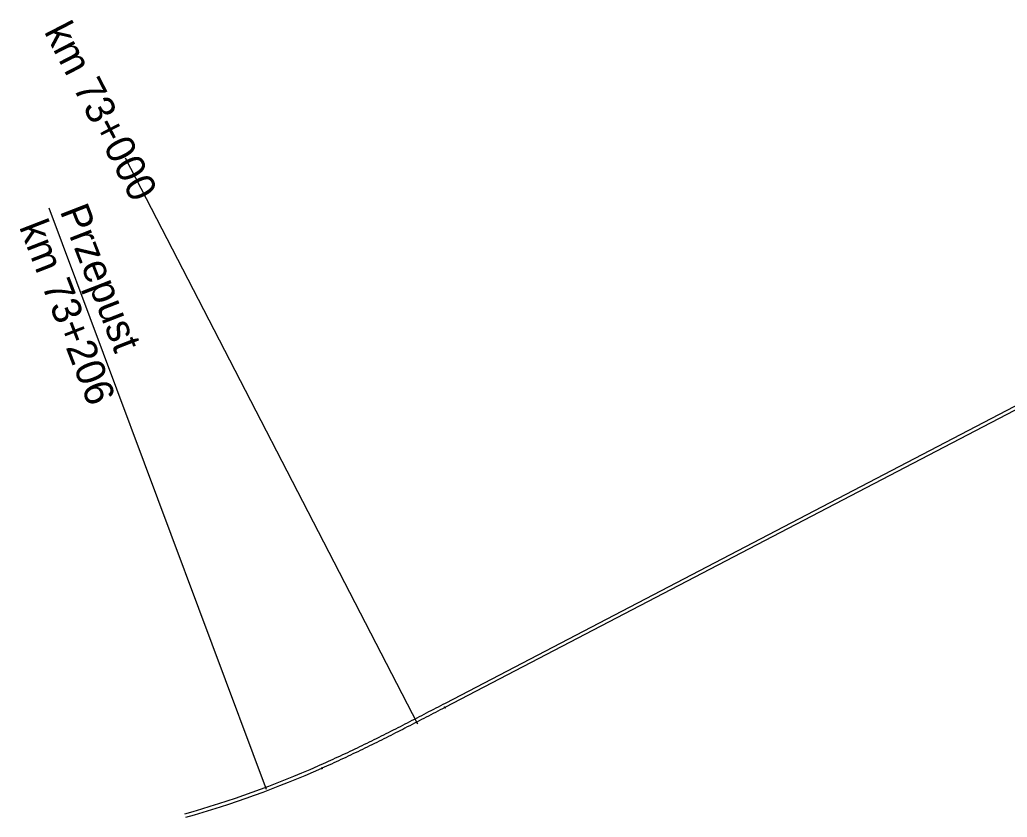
# Model space of a CAD drawing. Extents: x 6540591 to 6566579, y 5525343 to 5532423.
# Drawn here: x 6546011 to 6547196, y 5525886 to 5526843 of the extents above; entities that cross this region are included whole.
import ezdxf

# ---------------------------------------------------------------- set-up
doc = ezdxf.new("R2010")
doc.units = 0
for name, color, linetype in [('IR_ps_geometria', 7, 'Continuous'), ('TOR_PS_OPIS_T-hektometry projektowane', 7, 'Continuous'), ('TOR_PS_OPIS_T-opisy dodatkowe', 7, 'Continuous'), ('TOR_PS_T-tory projektowane', 7, 'Continuous')]:
    doc.layers.add(name, color=color, linetype=linetype)

msp = doc.modelspace()

# ---------------------------------------------------------------- linework, layer by layer
at = {"layer": 'IR_ps_geometria'}
for points in [[(6546521.1, 5526017.4), (6546521.2, 5526017.2), (6546521.3, 5526017.2), (6546521.3, 5526017.2), (6546521.3, 5526017.2), (6546521.4, 5526017.2), (6546521.4, 5526017.2), (6546521.4, 5526017.2), (6546521.4, 5526017.2), (6546521.5, 5526017.2), (6546521.5, 5526017.2), (6546521.5, 5526017.1), (6546521.5, 5526017.1), (6546521.6, 5526017.1), (6546521.6, 5526017), (6546521.6, 5526017), (6546521.6, 5526017), (6546521.6, 5526016.9), (6546521.6, 5526016.9), (6546521.6, 5526016.9), (6546521.6, 5526016.9), (6546521.6, 5526016.8), (6546521.5, 5526016.8), (6546521.5, 5526016.8), (6546521.5, 5526016.8), (6546521.5, 5526016.7), (6546521.4, 5526016.7), (6546521.4, 5526016.7), (6546521.4, 5526016.7), (6546521.3, 5526016.7), (6546521.3, 5526016.7), (6546521.3, 5526016.7), (6546521.2, 5526016.7), (6546521.2, 5526016.7), (6546521.2, 5526016.8), (6546521.2, 5526016.8), (6546521.1, 5526016.8), (6546521.1, 5526016.8), (6546521.1, 5526016.9), (6546521.1, 5526016.9), (6546521.1, 5526016.9), (6546521.1, 5526017), (6546521.1, 5526017), (6546521.1, 5526017), (6546521.1, 5526017.1), (6546521.1, 5526017.1), (6546521.1, 5526017.1), (6546521.2, 5526017.1), (6546521.2, 5526017.2), (6546521.2, 5526017.2), (6546521, 5526017.6), (6546521, 5526017.6), (6546520.9, 5526017.6), (6546520.9, 5526017.6), (6546520.9, 5526017.6), (6546520.8, 5526017.6), (6546520.8, 5526017.6), (6546520.8, 5526017.6), (6546520.7, 5526017.6), (6546520.7, 5526017.7), (6546520.7, 5526017.7), (6546520.7, 5526017.7), (6546520.7, 5526017.7), (6546520.6, 5526017.8), (6546520.6, 5526017.8), (6546520.6, 5526017.8), (6546520.6, 5526017.9), (6546520.6, 5526017.9), (6546520.6, 5526017.9), (6546520.7, 5526018), (6546520.7, 5526018), (6546520.7, 5526018), (6546520.7, 5526018), (6546520.7, 5526018.1), (6546520.8, 5526018.1), (6546520.8, 5526018.1), (6546520.8, 5526018.1), (6546520.9, 5526018.1), (6546520.9, 5526018.1), (6546520.9, 5526018.1), (6546521, 5526018.1), (6546521, 5526018.1), (6546521, 5526018.1), (6546521, 5526018), (6546521.1, 5526018), (6546521.1, 5526018), (6546521.1, 5526018), (6546521.1, 5526017.9), (6546521.1, 5526017.9), (6546521.1, 5526017.9), (6546521.1, 5526017.8), (6546521.1, 5526017.8), (6546521.1, 5526017.8), (6546521.1, 5526017.7), (6546521.1, 5526017.7), (6546521.1, 5526017.7), (6546521, 5526017.7), (6546521, 5526017.6), (6546521, 5526017.6)], [(6546521.1, 5526017.4), (6546521.2, 5526017.2), (6546521.3, 5526017.2), (6546521.3, 5526017.2), (6546521.3, 5526017.2), (6546521.4, 5526017.2), (6546521.4, 5526017.2), (6546521.4, 5526017.2), (6546521.4, 5526017.2), (6546521.5, 5526017.2), (6546521.5, 5526017.2), (6546521.5, 5526017.1), (6546521.5, 5526017.1), (6546521.6, 5526017.1), (6546521.6, 5526017), (6546521.6, 5526017), (6546521.6, 5526017), (6546521.6, 5526016.9), (6546521.6, 5526016.9), (6546521.6, 5526016.9), (6546521.6, 5526016.9), (6546521.6, 5526016.8), (6546521.5, 5526016.8), (6546521.5, 5526016.8), (6546521.5, 5526016.8), (6546521.5, 5526016.7), (6546521.4, 5526016.7), (6546521.4, 5526016.7), (6546521.4, 5526016.7), (6546521.3, 5526016.7), (6546521.3, 5526016.7), (6546521.3, 5526016.7), (6546521.2, 5526016.7), (6546521.2, 5526016.7), (6546521.2, 5526016.8), (6546521.2, 5526016.8), (6546521.1, 5526016.8), (6546521.1, 5526016.8), (6546521.1, 5526016.9), (6546521.1, 5526016.9), (6546521.1, 5526016.9), (6546521.1, 5526017), (6546521.1, 5526017), (6546521.1, 5526017), (6546521.1, 5526017.1), (6546521.1, 5526017.1), (6546521.1, 5526017.1), (6546521.2, 5526017.1), (6546521.2, 5526017.2), (6546521.2, 5526017.2), (6546521, 5526017.6), (6546521, 5526017.6), (6546520.9, 5526017.6), (6546520.9, 5526017.6), (6546520.9, 5526017.6), (6546520.8, 5526017.6), (6546520.8, 5526017.6), (6546520.8, 5526017.6), (6546520.7, 5526017.6), (6546520.7, 5526017.7), (6546520.7, 5526017.7), (6546520.7, 5526017.7), (6546520.7, 5526017.7), (6546520.6, 5526017.8), (6546520.6, 5526017.8), (6546520.6, 5526017.8), (6546520.6, 5526017.9), (6546520.6, 5526017.9), (6546520.6, 5526017.9), (6546520.7, 5526018), (6546520.7, 5526018), (6546520.7, 5526018), (6546520.7, 5526018), (6546520.7, 5526018.1), (6546520.8, 5526018.1), (6546520.8, 5526018.1), (6546520.8, 5526018.1), (6546520.9, 5526018.1), (6546520.9, 5526018.1), (6546520.9, 5526018.1), (6546521, 5526018.1), (6546521, 5526018.1), (6546521, 5526018.1), (6546521, 5526018), (6546521.1, 5526018), (6546521.1, 5526018), (6546521.1, 5526018), (6546521.1, 5526017.9), (6546521.1, 5526017.9), (6546521.1, 5526017.9), (6546521.1, 5526017.8), (6546521.1, 5526017.8), (6546521.1, 5526017.8), (6546521.1, 5526017.7), (6546521.1, 5526017.7), (6546521.1, 5526017.7), (6546521, 5526017.7), (6546521, 5526017.6), (6546521, 5526017.6)], [(6546521.1, 5526017.4), (6546521.2, 5526017.2), (6546521.3, 5526017.2), (6546521.3, 5526017.2), (6546521.3, 5526017.2), (6546521.4, 5526017.2), (6546521.4, 5526017.2), (6546521.4, 5526017.2), (6546521.4, 5526017.2), (6546521.5, 5526017.2), (6546521.5, 5526017.2), (6546521.5, 5526017.1), (6546521.5, 5526017.1), (6546521.6, 5526017.1), (6546521.6, 5526017), (6546521.6, 5526017), (6546521.6, 5526017), (6546521.6, 5526016.9), (6546521.6, 5526016.9), (6546521.6, 5526016.9), (6546521.6, 5526016.9), (6546521.6, 5526016.8), (6546521.5, 5526016.8), (6546521.5, 5526016.8), (6546521.5, 5526016.8), (6546521.5, 5526016.7), (6546521.4, 5526016.7), (6546521.4, 5526016.7), (6546521.4, 5526016.7), (6546521.3, 5526016.7), (6546521.3, 5526016.7), (6546521.3, 5526016.7), (6546521.2, 5526016.7), (6546521.2, 5526016.7), (6546521.2, 5526016.8), (6546521.2, 5526016.8), (6546521.1, 5526016.8), (6546521.1, 5526016.8), (6546521.1, 5526016.9), (6546521.1, 5526016.9), (6546521.1, 5526016.9), (6546521.1, 5526017), (6546521.1, 5526017), (6546521.1, 5526017), (6546521.1, 5526017.1), (6546521.1, 5526017.1), (6546521.1, 5526017.1), (6546521.2, 5526017.1), (6546521.2, 5526017.2), (6546521.2, 5526017.2), (6546521, 5526017.6), (6546521, 5526017.6), (6546520.9, 5526017.6), (6546520.9, 5526017.6), (6546520.9, 5526017.6), (6546520.8, 5526017.6), (6546520.8, 5526017.6), (6546520.8, 5526017.6), (6546520.7, 5526017.6), (6546520.7, 5526017.7), (6546520.7, 5526017.7), (6546520.7, 5526017.7), (6546520.7, 5526017.7), (6546520.6, 5526017.8), (6546520.6, 5526017.8), (6546520.6, 5526017.8), (6546520.6, 5526017.9), (6546520.6, 5526017.9), (6546520.6, 5526017.9), (6546520.7, 5526018), (6546520.7, 5526018), (6546520.7, 5526018), (6546520.7, 5526018), (6546520.7, 5526018.1), (6546520.8, 5526018.1), (6546520.8, 5526018.1), (6546520.8, 5526018.1), (6546520.9, 5526018.1), (6546520.9, 5526018.1), (6546520.9, 5526018.1), (6546521, 5526018.1), (6546521, 5526018.1), (6546521, 5526018.1), (6546521, 5526018), (6546521.1, 5526018), (6546521.1, 5526018), (6546521.1, 5526018), (6546521.1, 5526017.9), (6546521.1, 5526017.9), (6546521.1, 5526017.9), (6546521.1, 5526017.8), (6546521.1, 5526017.8), (6546521.1, 5526017.8), (6546521.1, 5526017.7), (6546521.1, 5526017.7), (6546521.1, 5526017.7), (6546521, 5526017.7), (6546521, 5526017.6), (6546521, 5526017.6)], [(6546521.1, 5526017.4), (6546521.2, 5526017.2), (6546521.3, 5526017.2), (6546521.3, 5526017.2), (6546521.3, 5526017.2), (6546521.4, 5526017.2), (6546521.4, 5526017.2), (6546521.4, 5526017.2), (6546521.4, 5526017.2), (6546521.5, 5526017.2), (6546521.5, 5526017.2), (6546521.5, 5526017.1), (6546521.5, 5526017.1), (6546521.6, 5526017.1), (6546521.6, 5526017), (6546521.6, 5526017), (6546521.6, 5526017), (6546521.6, 5526016.9), (6546521.6, 5526016.9), (6546521.6, 5526016.9), (6546521.6, 5526016.9), (6546521.6, 5526016.8), (6546521.5, 5526016.8), (6546521.5, 5526016.8), (6546521.5, 5526016.8), (6546521.5, 5526016.7), (6546521.4, 5526016.7), (6546521.4, 5526016.7), (6546521.4, 5526016.7), (6546521.3, 5526016.7), (6546521.3, 5526016.7), (6546521.3, 5526016.7), (6546521.2, 5526016.7), (6546521.2, 5526016.7), (6546521.2, 5526016.8), (6546521.2, 5526016.8), (6546521.1, 5526016.8), (6546521.1, 5526016.8), (6546521.1, 5526016.9), (6546521.1, 5526016.9), (6546521.1, 5526016.9), (6546521.1, 5526017), (6546521.1, 5526017), (6546521.1, 5526017), (6546521.1, 5526017.1), (6546521.1, 5526017.1), (6546521.1, 5526017.1), (6546521.2, 5526017.1), (6546521.2, 5526017.2), (6546521.2, 5526017.2), (6546521, 5526017.6), (6546521, 5526017.6), (6546520.9, 5526017.6), (6546520.9, 5526017.6), (6546520.9, 5526017.6), (6546520.8, 5526017.6), (6546520.8, 5526017.6), (6546520.8, 5526017.6), (6546520.7, 5526017.6), (6546520.7, 5526017.7), (6546520.7, 5526017.7), (6546520.7, 5526017.7), (6546520.7, 5526017.7), (6546520.6, 5526017.8), (6546520.6, 5526017.8), (6546520.6, 5526017.8), (6546520.6, 5526017.9), (6546520.6, 5526017.9), (6546520.6, 5526017.9), (6546520.7, 5526018), (6546520.7, 5526018), (6546520.7, 5526018), (6546520.7, 5526018), (6546520.7, 5526018.1), (6546520.8, 5526018.1), (6546520.8, 5526018.1), (6546520.8, 5526018.1), (6546520.9, 5526018.1), (6546520.9, 5526018.1), (6546520.9, 5526018.1), (6546521, 5526018.1), (6546521, 5526018.1), (6546521, 5526018.1), (6546521, 5526018), (6546521.1, 5526018), (6546521.1, 5526018), (6546521.1, 5526018), (6546521.1, 5526017.9), (6546521.1, 5526017.9), (6546521.1, 5526017.9), (6546521.1, 5526017.8), (6546521.1, 5526017.8), (6546521.1, 5526017.8), (6546521.1, 5526017.7), (6546521.1, 5526017.7), (6546521.1, 5526017.7), (6546521, 5526017.7), (6546521, 5526017.6), (6546521, 5526017.6)], [(6546373.2, 5525944.4), (6546373.3, 5525944.1), (6546373.3, 5525944.2), (6546373.4, 5525944.2), (6546373.4, 5525944.2), (6546373.4, 5525944.2), (6546373.4, 5525944.2), (6546373.5, 5525944.1), (6546373.5, 5525944.1), (6546373.5, 5525944.1), (6546373.6, 5525944.1), (6546373.6, 5525944.1), (6546373.6, 5525944), (6546373.6, 5525944), (6546373.6, 5525944), (6546373.6, 5525943.9), (6546373.6, 5525943.9), (6546373.6, 5525943.9), (6546373.6, 5525943.9), (6546373.6, 5525943.8), (6546373.6, 5525943.8), (6546373.6, 5525943.8), (6546373.6, 5525943.7), (6546373.5, 5525943.7), (6546373.5, 5525943.7), (6546373.5, 5525943.7), (6546373.5, 5525943.7), (6546373.4, 5525943.7), (6546373.4, 5525943.7), (6546373.4, 5525943.7), (6546373.3, 5525943.7), (6546373.3, 5525943.7), (6546373.3, 5525943.7), (6546373.2, 5525943.7), (6546373.2, 5525943.7), (6546373.2, 5525943.8), (6546373.2, 5525943.8), (6546373.2, 5525943.8), (6546373.1, 5525943.8), (6546373.1, 5525943.9), (6546373.1, 5525943.9), (6546373.1, 5525943.9), (6546373.1, 5525944), (6546373.2, 5525944), (6546373.2, 5525944), (6546373.2, 5525944.1), (6546373.2, 5525944.1), (6546373.2, 5525944.1), (6546373.3, 5525944.1), (6546373.3, 5525944.1), (6546373.1, 5525944.6), (6546373.1, 5525944.6), (6546373, 5525944.6), (6546373, 5525944.6), (6546373, 5525944.6), (6546372.9, 5525944.6), (6546372.9, 5525944.6), (6546372.9, 5525944.6), (6546372.8, 5525944.6), (6546372.8, 5525944.6), (6546372.8, 5525944.7), (6546372.8, 5525944.7), (6546372.8, 5525944.7), (6546372.7, 5525944.8), (6546372.7, 5525944.8), (6546372.7, 5525944.8), (6546372.7, 5525944.9), (6546372.7, 5525944.9), (6546372.8, 5525944.9), (6546372.8, 5525944.9), (6546372.8, 5525945), (6546372.8, 5525945), (6546372.8, 5525945), (6546372.9, 5525945), (6546372.9, 5525945.1), (6546372.9, 5525945.1), (6546372.9, 5525945.1), (6546373, 5525945.1), (6546373, 5525945.1), (6546373, 5525945.1), (6546373.1, 5525945.1), (6546373.1, 5525945), (6546373.1, 5525945), (6546373.2, 5525945), (6546373.2, 5525945), (6546373.2, 5525945), (6546373.2, 5525944.9), (6546373.2, 5525944.9), (6546373.2, 5525944.9), (6546373.2, 5525944.8), (6546373.2, 5525944.8), (6546373.2, 5525944.8), (6546373.2, 5525944.7), (6546373.2, 5525944.7), (6546373.2, 5525944.7), (6546373.2, 5525944.7), (6546373.1, 5525944.6), (6546373.1, 5525944.6), (6546373.1, 5525944.6)], [(6546373.2, 5525944.4), (6546373.3, 5525944.1), (6546373.3, 5525944.2), (6546373.4, 5525944.2), (6546373.4, 5525944.2), (6546373.4, 5525944.2), (6546373.4, 5525944.2), (6546373.5, 5525944.1), (6546373.5, 5525944.1), (6546373.5, 5525944.1), (6546373.6, 5525944.1), (6546373.6, 5525944.1), (6546373.6, 5525944), (6546373.6, 5525944), (6546373.6, 5525944), (6546373.6, 5525943.9), (6546373.6, 5525943.9), (6546373.6, 5525943.9), (6546373.6, 5525943.9), (6546373.6, 5525943.8), (6546373.6, 5525943.8), (6546373.6, 5525943.8), (6546373.6, 5525943.7), (6546373.5, 5525943.7), (6546373.5, 5525943.7), (6546373.5, 5525943.7), (6546373.5, 5525943.7), (6546373.4, 5525943.7), (6546373.4, 5525943.7), (6546373.4, 5525943.7), (6546373.3, 5525943.7), (6546373.3, 5525943.7), (6546373.3, 5525943.7), (6546373.2, 5525943.7), (6546373.2, 5525943.7), (6546373.2, 5525943.8), (6546373.2, 5525943.8), (6546373.2, 5525943.8), (6546373.1, 5525943.8), (6546373.1, 5525943.9), (6546373.1, 5525943.9), (6546373.1, 5525943.9), (6546373.1, 5525944), (6546373.2, 5525944), (6546373.2, 5525944), (6546373.2, 5525944.1), (6546373.2, 5525944.1), (6546373.2, 5525944.1), (6546373.3, 5525944.1), (6546373.3, 5525944.1), (6546373.1, 5525944.6), (6546373.1, 5525944.6), (6546373, 5525944.6), (6546373, 5525944.6), (6546373, 5525944.6), (6546372.9, 5525944.6), (6546372.9, 5525944.6), (6546372.9, 5525944.6), (6546372.8, 5525944.6), (6546372.8, 5525944.6), (6546372.8, 5525944.7), (6546372.8, 5525944.7), (6546372.8, 5525944.7), (6546372.7, 5525944.8), (6546372.7, 5525944.8), (6546372.7, 5525944.8), (6546372.7, 5525944.9), (6546372.7, 5525944.9), (6546372.8, 5525944.9), (6546372.8, 5525944.9), (6546372.8, 5525945), (6546372.8, 5525945), (6546372.8, 5525945), (6546372.9, 5525945), (6546372.9, 5525945.1), (6546372.9, 5525945.1), (6546372.9, 5525945.1), (6546373, 5525945.1), (6546373, 5525945.1), (6546373, 5525945.1), (6546373.1, 5525945.1), (6546373.1, 5525945), (6546373.1, 5525945), (6546373.2, 5525945), (6546373.2, 5525945), (6546373.2, 5525945), (6546373.2, 5525944.9), (6546373.2, 5525944.9), (6546373.2, 5525944.9), (6546373.2, 5525944.8), (6546373.2, 5525944.8), (6546373.2, 5525944.8), (6546373.2, 5525944.7), (6546373.2, 5525944.7), (6546373.2, 5525944.7), (6546373.2, 5525944.7), (6546373.1, 5525944.6), (6546373.1, 5525944.6), (6546373.1, 5525944.6)], [(6546373.2, 5525944.4), (6546373.3, 5525944.1), (6546373.3, 5525944.2), (6546373.4, 5525944.2), (6546373.4, 5525944.2), (6546373.4, 5525944.2), (6546373.4, 5525944.2), (6546373.5, 5525944.1), (6546373.5, 5525944.1), (6546373.5, 5525944.1), (6546373.6, 5525944.1), (6546373.6, 5525944.1), (6546373.6, 5525944), (6546373.6, 5525944), (6546373.6, 5525944), (6546373.6, 5525943.9), (6546373.6, 5525943.9), (6546373.6, 5525943.9), (6546373.6, 5525943.9), (6546373.6, 5525943.8), (6546373.6, 5525943.8), (6546373.6, 5525943.8), (6546373.6, 5525943.7), (6546373.5, 5525943.7), (6546373.5, 5525943.7), (6546373.5, 5525943.7), (6546373.5, 5525943.7), (6546373.4, 5525943.7), (6546373.4, 5525943.7), (6546373.4, 5525943.7), (6546373.3, 5525943.7), (6546373.3, 5525943.7), (6546373.3, 5525943.7), (6546373.2, 5525943.7), (6546373.2, 5525943.7), (6546373.2, 5525943.8), (6546373.2, 5525943.8), (6546373.2, 5525943.8), (6546373.1, 5525943.8), (6546373.1, 5525943.9), (6546373.1, 5525943.9), (6546373.1, 5525943.9), (6546373.1, 5525944), (6546373.2, 5525944), (6546373.2, 5525944), (6546373.2, 5525944.1), (6546373.2, 5525944.1), (6546373.2, 5525944.1), (6546373.3, 5525944.1), (6546373.3, 5525944.1), (6546373.1, 5525944.6), (6546373.1, 5525944.6), (6546373, 5525944.6), (6546373, 5525944.6), (6546373, 5525944.6), (6546372.9, 5525944.6), (6546372.9, 5525944.6), (6546372.9, 5525944.6), (6546372.8, 5525944.6), (6546372.8, 5525944.6), (6546372.8, 5525944.7), (6546372.8, 5525944.7), (6546372.8, 5525944.7), (6546372.7, 5525944.8), (6546372.7, 5525944.8), (6546372.7, 5525944.8), (6546372.7, 5525944.9), (6546372.7, 5525944.9), (6546372.8, 5525944.9), (6546372.8, 5525944.9), (6546372.8, 5525945), (6546372.8, 5525945), (6546372.8, 5525945), (6546372.9, 5525945), (6546372.9, 5525945.1), (6546372.9, 5525945.1), (6546372.9, 5525945.1), (6546373, 5525945.1), (6546373, 5525945.1), (6546373, 5525945.1), (6546373.1, 5525945.1), (6546373.1, 5525945), (6546373.1, 5525945), (6546373.2, 5525945), (6546373.2, 5525945), (6546373.2, 5525945), (6546373.2, 5525944.9), (6546373.2, 5525944.9), (6546373.2, 5525944.9), (6546373.2, 5525944.8), (6546373.2, 5525944.8), (6546373.2, 5525944.8), (6546373.2, 5525944.7), (6546373.2, 5525944.7), (6546373.2, 5525944.7), (6546373.2, 5525944.7), (6546373.1, 5525944.6), (6546373.1, 5525944.6), (6546373.1, 5525944.6)], [(6546373.2, 5525944.4), (6546373.3, 5525944.1), (6546373.3, 5525944.2), (6546373.4, 5525944.2), (6546373.4, 5525944.2), (6546373.4, 5525944.2), (6546373.4, 5525944.2), (6546373.5, 5525944.1), (6546373.5, 5525944.1), (6546373.5, 5525944.1), (6546373.6, 5525944.1), (6546373.6, 5525944.1), (6546373.6, 5525944), (6546373.6, 5525944), (6546373.6, 5525944), (6546373.6, 5525943.9), (6546373.6, 5525943.9), (6546373.6, 5525943.9), (6546373.6, 5525943.9), (6546373.6, 5525943.8), (6546373.6, 5525943.8), (6546373.6, 5525943.8), (6546373.6, 5525943.7), (6546373.5, 5525943.7), (6546373.5, 5525943.7), (6546373.5, 5525943.7), (6546373.5, 5525943.7), (6546373.4, 5525943.7), (6546373.4, 5525943.7), (6546373.4, 5525943.7), (6546373.3, 5525943.7), (6546373.3, 5525943.7), (6546373.3, 5525943.7), (6546373.2, 5525943.7), (6546373.2, 5525943.7), (6546373.2, 5525943.8), (6546373.2, 5525943.8), (6546373.2, 5525943.8), (6546373.1, 5525943.8), (6546373.1, 5525943.9), (6546373.1, 5525943.9), (6546373.1, 5525943.9), (6546373.1, 5525944), (6546373.2, 5525944), (6546373.2, 5525944), (6546373.2, 5525944.1), (6546373.2, 5525944.1), (6546373.2, 5525944.1), (6546373.3, 5525944.1), (6546373.3, 5525944.1), (6546373.1, 5525944.6), (6546373.1, 5525944.6), (6546373, 5525944.6), (6546373, 5525944.6), (6546373, 5525944.6), (6546372.9, 5525944.6), (6546372.9, 5525944.6), (6546372.9, 5525944.6), (6546372.8, 5525944.6), (6546372.8, 5525944.6), (6546372.8, 5525944.7), (6546372.8, 5525944.7), (6546372.8, 5525944.7), (6546372.7, 5525944.8), (6546372.7, 5525944.8), (6546372.7, 5525944.8), (6546372.7, 5525944.9), (6546372.7, 5525944.9), (6546372.8, 5525944.9), (6546372.8, 5525944.9), (6546372.8, 5525945), (6546372.8, 5525945), (6546372.8, 5525945), (6546372.9, 5525945), (6546372.9, 5525945.1), (6546372.9, 5525945.1), (6546372.9, 5525945.1), (6546373, 5525945.1), (6546373, 5525945.1), (6546373, 5525945.1), (6546373.1, 5525945.1), (6546373.1, 5525945), (6546373.1, 5525945), (6546373.2, 5525945), (6546373.2, 5525945), (6546373.2, 5525945), (6546373.2, 5525944.9), (6546373.2, 5525944.9), (6546373.2, 5525944.9), (6546373.2, 5525944.8), (6546373.2, 5525944.8), (6546373.2, 5525944.8), (6546373.2, 5525944.7), (6546373.2, 5525944.7), (6546373.2, 5525944.7), (6546373.2, 5525944.7), (6546373.1, 5525944.6), (6546373.1, 5525944.6), (6546373.1, 5525944.6)]]:
    msp.add_lwpolyline(points, close=True, dxfattribs=at)
at = {"layer": 'TOR_PS_OPIS_T-hektometry projektowane'}
msp.add_lwpolyline([(6546488.5, 5525997.2), (6546137.4, 5526676.9)], dxfattribs=at)
at = {"layer": 'TOR_PS_OPIS_T-opisy dodatkowe'}
msp.add_line((6546045.5, 5526617), (6546306.4, 5525919.2), dxfattribs=at)
at = {"layer": 'TOR_PS_T-tory projektowane'}
for p, q in [((6547790.1, 5526678.9), (6546521.1, 5526017.4)), ((6547788.9, 5526683.1), (6546521.5, 5526022.3))]:
    msp.add_line(p, q, dxfattribs=at)
for points in [[(6546521.5, 5526022.3), (6546518.6, 5526020.9), (6546515.8, 5526019.4), (6546513, 5526017.9), (6546510.1, 5526016.4), (6546507.3, 5526014.9), (6546504.4, 5526013.4), (6546501.6, 5526012), (6546498.7, 5526010.5), (6546495.9, 5526009), (6546493, 5526007.5), (6546490.2, 5526006.1), (6546487.3, 5526004.6), (6546484.5, 5526003.1), (6546481.6, 5526001.6), (6546478.8, 5526000.2), (6546475.9, 5525998.7), (6546473.1, 5525997.2), (6546470.2, 5525995.8), (6546467.4, 5525994.3), (6546464.5, 5525992.9), (6546461.6, 5525991.4), (6546458.8, 5525990), (6546455.9, 5525988.5), (6546453.1, 5525987.1), (6546450.2, 5525985.6), (6546447.3, 5525984.2), (6546444.5, 5525982.8), (6546441.6, 5525981.3), (6546438.7, 5525979.9), (6546435.8, 5525978.5), (6546433, 5525977.1), (6546430.1, 5525975.6), (6546427.2, 5525974.2), (6546424.3, 5525972.8), (6546421.4, 5525971.4), (6546418.5, 5525970), (6546415.7, 5525968.6), (6546412.8, 5525967.3), (6546409.9, 5525965.9), (6546407, 5525964.5), (6546404.1, 5525963.1), (6546401.2, 5525961.8), (6546398.3, 5525960.4), (6546395.3, 5525959.1), (6546392.4, 5525957.7), (6546389.5, 5525956.4), (6546386.6, 5525955), (6546383.7, 5525953.7), (6546380.8, 5525952.4), (6546377.8, 5525951.1), (6546374.9, 5525949.8), (6546372, 5525948.5), (6546369, 5525947.2)], [(6546521.1, 5526017.4), (6546518.3, 5526015.9), (6546515.5, 5526014.5), (6546512.7, 5526013), (6546509.9, 5526011.5), (6546507, 5526010.1), (6546504.2, 5526008.6), (6546501.4, 5526007.1), (6546498.6, 5526005.7), (6546495.8, 5526004.2), (6546493, 5526002.8), (6546490.1, 5526001.3), (6546487.3, 5525999.8), (6546484.5, 5525998.4), (6546481.7, 5525996.9), (6546478.9, 5525995.5), (6546476, 5525994), (6546473.2, 5525992.6), (6546470.4, 5525991.1), (6546467.6, 5525989.7), (6546464.7, 5525988.2), (6546461.9, 5525986.8), (6546459.1, 5525985.4), (6546456.3, 5525983.9), (6546453.4, 5525982.5), (6546450.6, 5525981.1), (6546447.7, 5525979.7), (6546444.9, 5525978.2), (6546442.1, 5525976.8), (6546439.2, 5525975.4), (6546436.4, 5525974), (6546433.5, 5525972.6), (6546430.7, 5525971.2), (6546427.8, 5525969.8), (6546425, 5525968.4), (6546422.1, 5525967), (6546419.3, 5525965.7), (6546416.4, 5525964.3), (6546413.5, 5525962.9), (6546410.7, 5525961.6), (6546407.8, 5525960.2), (6546404.9, 5525958.8), (6546402.1, 5525957.5), (6546399.2, 5525956.2), (6546396.3, 5525954.8), (6546393.4, 5525953.5), (6546390.6, 5525952.2), (6546387.7, 5525950.9), (6546384.8, 5525949.5), (6546381.9, 5525948.2), (6546379, 5525946.9), (6546376.1, 5525945.7), (6546373.2, 5525944.4)]]:
    msp.add_lwpolyline(points, dxfattribs=at)
for centre, radius, start, end in [((6545867.8, 5527092.3), 1250, 285.8298, 293.6381), ((6545867.8, 5527092), 1254, 285.8325, 293.7647)]:
    msp.add_arc(centre, radius, start, end, dxfattribs=at)

# ---------------------------------------------------------------- texts
at = {"layer": 'TOR_PS_OPIS_T-hektometry projektowane'}
msp.add_text('km 73+000', height=35, rotation=297.3213, dxfattribs=at).set_placement((6546039.3, 5526828.8))
at = {"layer": 'TOR_PS_OPIS_T-opisy dodatkowe'}
for s, p in [('Przepust', (6546058.4, 5526613.4)), ('km 73+206', (6546009.5, 5526594.4))]:
    msp.add_text(s, height=35, rotation=291.1976, dxfattribs=at).set_placement(p)

doc.saveas('drawing.dxf')
